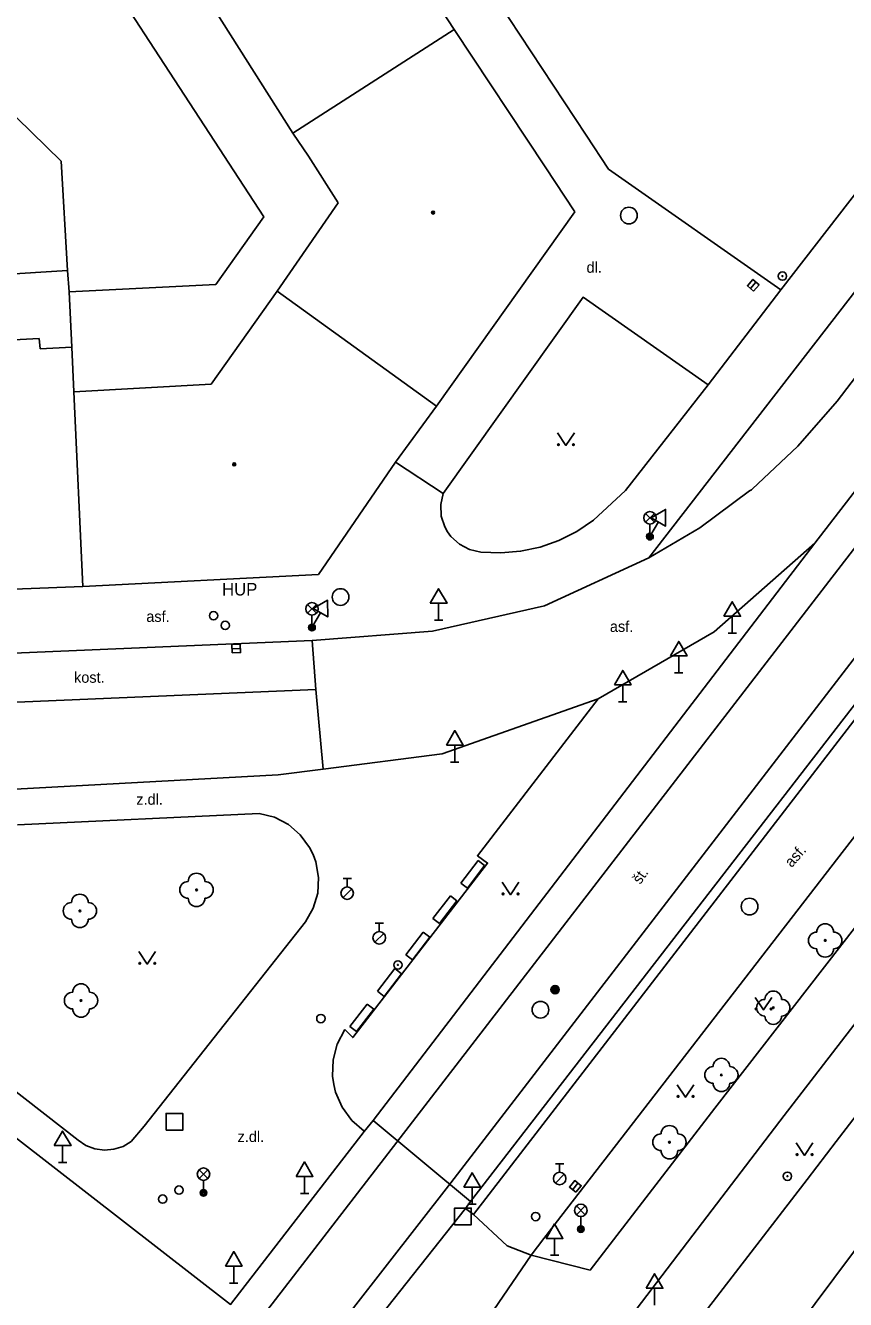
# Model space of a CAD drawing. Extents: x -598932 to -598196, y -1162207 to -1161504.
# Drawn here: x -598832.1 to -598782.9, y -1162047.2 to -1161970.8 of the extents above; entities that cross this region are included whole.
import ezdxf

# ---------------------------------------------------------------- set-up
doc = ezdxf.new("R2010")
doc.units = 0
for name, color, linetype in [('Level 22', 7, 'Continuous'), ('Level 25', 7, 'Continuous'), ('Level 26', 7, 'Continuous'), ('Level 27', 7, 'Continuous'), ('Level 28', 7, 'Continuous'), ('Level 33', 7, 'Continuous'), ('Level 34', 7, 'Continuous'), ('Level 36', 7, 'Continuous'), ('Level 39', 7, 'Continuous'), ('specificka linie pasportu komunikaci', 7, 'Continuous'), ('TM - budovy zdene_ betonove - VP', 7, 'Continuous'), ('TM - chodniky - VP', 7, 'Continuous'), ('TM - komunikace - VP', 7, 'Continuous'), ('TM - MHD - osa koleji', 7, 'Continuous'), ('TM - popis objektu', 7, 'Continuous'), ('TM - popis povrchu', 7, 'Continuous'), ('TM - rozhrani ploch obecne - VP', 7, 'Continuous')]:
    doc.layers.add(name, color=color, linetype=linetype)

msp = doc.modelspace()

# ---------------------------------------------------------------- linework, layer by layer
at = {"layer": 'Level 22'}
for centre in [(-598821.81, -1162022.62), (-598828.8, -1162023.88), (-598784.14, -1162025.65), (-598828.73, -1162029.25), (-598787.25, -1162029.68), (-598790.36, -1162033.71), (-598793.47, -1162037.74)]:
    msp.add_circle(centre, 0.05, dxfattribs=at)
for centre, start, end in [((-598821.81, -1162022.12), 0, 180), ((-598822.31, -1162022.62), 90, 270), ((-598821.31, -1162022.62), 270, 90), ((-598828.8, -1162023.38), 0, 180), ((-598821.81, -1162023.12), 180, 0), ((-598829.3, -1162023.88), 90, 270), ((-598828.3, -1162023.88), 270, 90), ((-598828.8, -1162024.38), 180, 0), ((-598784.14, -1162025.15), 0, 180), ((-598784.64, -1162025.65), 90, 270), ((-598783.64, -1162025.65), 270, 90), ((-598784.14, -1162026.15), 180, 0), ((-598828.73, -1162028.75), 0, 180), ((-598829.23, -1162029.25), 90, 270), ((-598828.23, -1162029.25), 270, 90), ((-598787.75, -1162029.68), 90, 270), ((-598787.25, -1162029.18), 0, 180), ((-598786.75, -1162029.68), 270, 90), ((-598828.73, -1162029.75), 180, 0), ((-598787.25, -1162030.18), 180, 0), ((-598790.36, -1162033.21), 0, 180), ((-598790.86, -1162033.71), 90, 270), ((-598789.86, -1162033.71), 270, 90), ((-598790.36, -1162034.21), 180, 0), ((-598793.47, -1162037.24), 0, 180), ((-598793.97, -1162037.74), 90, 270), ((-598792.97, -1162037.74), 270, 90), ((-598793.47, -1162038.24), 180, 0)]:
    msp.add_arc(centre, 0.5, start, end, dxfattribs=at)
at = {"layer": 'Level 25'}
for centre, radius in [((-598786.7, -1161985.84), 0.25), ((-598786.7, -1161985.84), 0.0303), ((-598809.74, -1162027.12), 0.25), ((-598809.74, -1162027.12), 0.0303), ((-598800.32, -1162028.6), 0.25), ((-598800.32, -1162028.6), 0.2), ((-598800.32, -1162028.6), 0.15), ((-598800.32, -1162028.6), 0.1), ((-598800.32, -1162028.6), 0.05), ((-598786.4, -1162039.78), 0.25), ((-598786.4, -1162039.78), 0.0303)]:
    msp.add_circle(centre, radius, dxfattribs=at)
at = {"layer": 'Level 26'}
for points in [[(-598823.63, -1162037.02), (-598822.63, -1162037.02), (-598822.63, -1162036.02), (-598823.63, -1162036.02)], [(-598806.35, -1162042.69), (-598805.35, -1162042.69), (-598805.35, -1162041.69), (-598806.35, -1162041.69)]]:
    msp.add_lwpolyline(points, close=True, dxfattribs=at)
at = {"layer": 'Level 27'}
for p, q in [((-598788.615, -1161986.578), (-598788.285, -1161986.202)), ((-598819.68, -1162008.169), (-598819.18, -1162008.15)), ((-598799.267, -1162040.584), (-598798.953, -1162040.196))]:
    msp.add_line(p, q, dxfattribs=at)
for points in [[(-598788.426, -1161986.743), (-598788.097, -1161986.366), (-598788.474, -1161986.037), (-598788.803, -1161986.414)], [(-598819.67, -1162008.419), (-598819.171, -1162008.4), (-598819.19, -1162007.901), (-598819.689, -1162007.92)], [(-598799.073, -1162040.742), (-598798.758, -1162040.353), (-598799.147, -1162040.038), (-598799.462, -1162040.427)]]:
    msp.add_lwpolyline(points, close=True, dxfattribs=at)
for centre in [(-598795.9, -1161982.21), (-598813.18, -1162005.07), (-598788.67, -1162023.62), (-598801.2, -1162029.8)]:
    msp.add_circle(centre, 0.5, dxfattribs=at)
at = {"layer": 'Level 28'}
for p, q in [((-598813.03, -1162021.945), (-598812.53, -1162021.945)), ((-598812.78, -1162022.445), (-598812.78, -1162021.945)), ((-598813.038, -1162023.092), (-598812.508, -1162022.562)), ((-598811.11, -1162024.615), (-598810.61, -1162024.615)), ((-598810.86, -1162025.115), (-598810.86, -1162024.615)), ((-598811.118, -1162025.762), (-598810.588, -1162025.232)), ((-598800.3, -1162039.045), (-598799.8, -1162039.045)), ((-598800.05, -1162039.545), (-598800.05, -1162039.045)), ((-598800.308, -1162040.192), (-598799.778, -1162039.662))]:
    msp.add_line(p, q, dxfattribs=at)
for centre, radius in [((-598820.79, -1162006.19), 0.25), ((-598820.09, -1162006.77), 0.25), ((-598812.78, -1162022.82), 0.375), ((-598810.86, -1162025.49), 0.375), ((-598814.36, -1162030.33), 0.25), ((-598800.05, -1162039.92), 0.375), ((-598822.86, -1162040.61), 0.25), ((-598823.84, -1162041.15), 0.25), ((-598801.49, -1162042.2), 0.25)]:
    msp.add_circle(centre, radius, dxfattribs=at)
at = {"layer": 'Level 33'}
for p, q in [((-598794.905, -1162000.59), (-598794.375, -1162000.06)), ((-598794.905, -1162000.06), (-598794.375, -1162000.59)), ((-598794.64, -1162000.7), (-598794.64, -1162001.45)), ((-598815.155, -1162006.04), (-598814.625, -1162005.51)), ((-598815.155, -1162005.51), (-598814.625, -1162006.04)), ((-598814.89, -1162006.15), (-598814.89, -1162006.9)), ((-598821.655, -1162039.92), (-598821.125, -1162039.39)), ((-598821.655, -1162039.39), (-598821.125, -1162039.92)), ((-598821.39, -1162040.03), (-598821.39, -1162040.78)), ((-598799.045, -1162042.09), (-598798.515, -1162041.56)), ((-598799.045, -1162041.56), (-598798.515, -1162042.09)), ((-598798.78, -1162042.2), (-598798.78, -1162042.95))]:
    msp.add_line(p, q, dxfattribs=at)
for centre, radius in [((-598794.64, -1162000.325), 0.375), ((-598794.64, -1162001.45), 0.2), ((-598794.64, -1162001.45), 0.145), ((-598794.64, -1162001.45), 0.0876), ((-598814.89, -1162005.775), 0.375), ((-598814.89, -1162006.9), 0.2), ((-598814.89, -1162006.9), 0.145), ((-598814.89, -1162006.9), 0.0876), ((-598821.39, -1162039.655), 0.375), ((-598821.39, -1162040.78), 0.2), ((-598821.39, -1162040.78), 0.145), ((-598821.39, -1162040.78), 0.0876), ((-598798.78, -1162041.825), 0.375), ((-598798.78, -1162042.95), 0.2), ((-598798.78, -1162042.95), 0.145), ((-598798.78, -1162042.95), 0.0876)]:
    msp.add_circle(centre, radius, dxfattribs=at)
at = {"layer": 'Level 34'}
for p, q in [((-598794.133, -1162000.567), (-598794.64, -1162001.45)), ((-598794.857, -1162001.326), (-598794.423, -1162001.574)), ((-598807.3, -1162005.442), (-598807.3, -1162006.46)), ((-598814.383, -1162006.017), (-598814.89, -1162006.9)), ((-598807.55, -1162006.46), (-598807.05, -1162006.46)), ((-598789.71, -1162006.222), (-598789.71, -1162007.24)), ((-598815.107, -1162006.776), (-598814.673, -1162007.024)), ((-598789.96, -1162007.24), (-598789.46, -1162007.24)), ((-598792.91, -1162008.602), (-598792.91, -1162009.62)), ((-598793.16, -1162009.62), (-598792.66, -1162009.62)), ((-598796.27, -1162010.332), (-598796.27, -1162011.35)), ((-598796.52, -1162011.35), (-598796.02, -1162011.35)), ((-598806.34, -1162013.942), (-598806.34, -1162014.96)), ((-598806.59, -1162014.96), (-598806.09, -1162014.96)), ((-598829.83, -1162037.942), (-598829.83, -1162038.96)), ((-598830.08, -1162038.96), (-598829.58, -1162038.96)), ((-598815.33, -1162039.792), (-598815.33, -1162040.81)), ((-598815.58, -1162040.81), (-598815.08, -1162040.81)), ((-598805.3, -1162040.442), (-598805.3, -1162041.46)), ((-598805.55, -1162041.46), (-598805.05, -1162041.46)), ((-598800.35, -1162043.502), (-598800.35, -1162044.52)), ((-598800.6, -1162044.52), (-598800.1, -1162044.52)), ((-598819.58, -1162045.162), (-598819.58, -1162046.18)), ((-598819.83, -1162046.18), (-598819.33, -1162046.18)), ((-598794.359, -1162046.492), (-598794.36, -1162047.51))]:
    msp.add_line(p, q, dxfattribs=at)
for points in [[(-598794.567, -1162000.318), (-598793.7, -1162000.816), (-598793.702, -1161999.816)], [(-598807.8, -1162005.442), (-598806.8, -1162005.442), (-598807.3, -1162004.576)], [(-598814.817, -1162005.768), (-598813.95, -1162006.266), (-598813.952, -1162005.266)], [(-598790.21, -1162006.222), (-598789.21, -1162006.222), (-598789.71, -1162005.356)], [(-598793.41, -1162008.602), (-598792.41, -1162008.602), (-598792.91, -1162007.736)], [(-598796.77, -1162010.332), (-598795.77, -1162010.332), (-598796.27, -1162009.466)], [(-598806.84, -1162013.942), (-598805.84, -1162013.942), (-598806.34, -1162013.076)], [(-598830.33, -1162037.942), (-598829.33, -1162037.942), (-598829.83, -1162037.076)], [(-598815.83, -1162039.792), (-598814.83, -1162039.792), (-598815.33, -1162038.926)], [(-598805.8, -1162040.442), (-598804.8, -1162040.442), (-598805.3, -1162039.576)], [(-598800.85, -1162043.502), (-598799.85, -1162043.502), (-598800.35, -1162042.636)], [(-598820.08, -1162045.162), (-598819.08, -1162045.162), (-598819.58, -1162044.296)], [(-598794.859, -1162046.492), (-598793.859, -1162046.492), (-598794.359, -1162045.626)]]:
    msp.add_lwpolyline(points, close=True, dxfattribs=at)
at = {"layer": 'Level 36'}
for points in [[(-598800.17, -1161995.24), (-598799.67, -1161995.99), (-598799.17, -1161995.24)], [(-598803.49, -1162022.16), (-598802.99, -1162022.91), (-598802.49, -1162022.16)], [(-598825.26, -1162026.32), (-598824.76, -1162027.07), (-598824.26, -1162026.32)], [(-598788.33, -1162029.06), (-598787.83, -1162029.81), (-598787.33, -1162029.06)], [(-598793, -1162034.3), (-598792.5, -1162035.05), (-598792, -1162034.3)], [(-598785.87, -1162037.78), (-598785.37, -1162038.53), (-598784.87, -1162037.78)]]:
    msp.add_lwpolyline(points, dxfattribs=at)
for centre in [(-598800.12, -1161995.94), (-598799.221, -1161995.94), (-598803.44, -1162022.86), (-598802.541, -1162022.86), (-598825.21, -1162027.02), (-598824.311, -1162027.02), (-598788.28, -1162029.76), (-598787.381, -1162029.76), (-598792.95, -1162035), (-598792.051, -1162035), (-598785.82, -1162038.48), (-598784.921, -1162038.48)]:
    msp.add_circle(centre, 0.05, dxfattribs=at)
at = {"layer": 'Level 39'}
for centre, radius in [((-598807.63, -1161982.03), 0.09), ((-598807.63, -1161982.03), 0.0398), ((-598819.55, -1161997.12), 0.09), ((-598819.55, -1161997.12), 0.0398)]:
    msp.add_circle(centre, radius, dxfattribs=at)
at = {"layer": 'specificka linie pasportu komunikaci'}
for points in [[(-598814.22, -1162015.38), (-598814.66, -1162010.61)], [(-598785.92, -1162048.98), (-598775.483, -1162035.027), (-598774.992, -1162034.371), (-598769.53, -1162027.073), (-598769.53, -1162027.07)], [(-598813.9, -1162052.09), (-598805.7, -1162041.71)], [(-598803.19, -1162043.96), (-598805.22, -1162042.08)], [(-598801.76, -1162044.51), (-598803.19, -1162043.96)]]:
    msp.add_lwpolyline(points, dxfattribs=at)
at = {"layer": 'TM - budovy zdene_ betonove - VP'}
for points in [[(-598816.04, -1161977.27), (-598825.31, -1161962.63)], [(-598811.5, -1161963.22), (-598806.37, -1161971.07)], [(-598806.37, -1161971.07), (-598816.04, -1161977.27)], [(-598806.37, -1161971.07), (-598800.92, -1161979.29), (-598799.14, -1161981.98)], [(-598815.09, -1161978.66), (-598816.04, -1161977.27)], [(-598813.32, -1161981.44), (-598815.09, -1161978.66)], [(-598816.98, -1161986.74), (-598813.32, -1161981.44)], [(-598799.14, -1161981.98), (-598807.43, -1161993.63)], [(-598820.93, -1161992.32), (-598816.98, -1161986.74)], [(-598807.43, -1161993.63), (-598816.98, -1161986.74)], [(-598836.62, -1161989.85), (-598831.24, -1161989.57)], [(-598831.24, -1161989.57), (-598831.18, -1161990.2)], [(-598831.18, -1161990.2), (-598829.29, -1161990.1)], [(-598829.29, -1161990.1), (-598829.17, -1161992.77)], [(-598829.17, -1161992.77), (-598820.93, -1161992.32)], [(-598828.63, -1162004.44), (-598829.17, -1161992.77)], [(-598807.43, -1161993.63), (-598809.88, -1161996.98)], [(-598809.88, -1161996.98), (-598814.51, -1162003.72)], [(-598814.51, -1162003.72), (-598828.63, -1162004.44)], [(-598828.63, -1162004.44), (-598844.65, -1162005.06)]]:
    msp.add_lwpolyline(points, dxfattribs=at)
at = {"layer": 'TM - chodniky - VP'}
for points in [[(-598807.03, -1161964.38), (-598798.47, -1161977.39), (-598797.13, -1161979.43), (-598786.79, -1161986.67)], [(-598786.79, -1161986.67), (-598781.28, -1161979.55)], [(-598778.8, -1161982.18), (-598794.7, -1162002.73)], [(-598791.15, -1161992.36), (-598798.65, -1161987.11), (-598807.03, -1161998.86)], [(-598798.03, -1162000.47), (-598796.1, -1161998.68), (-598791.15, -1161992.36)], [(-598804.78, -1162002.38), (-598805.45, -1162002.23), (-598806.059, -1162001.913), (-598806.565, -1162001.449), (-598806.77, -1162001.17), (-598806.935, -1162000.871), (-598807.143, -1162000.217), (-598807.175, -1161999.531), (-598807.03, -1161998.86)], [(-598798.03, -1162000.47), (-598799.022, -1162001.141), (-598800.091, -1162001.681), (-598801.22, -1162002.08), (-598802.39, -1162002.332), (-598803.584, -1162002.432), (-598804.78, -1162002.38)], [(-598811.23, -1162036.45), (-598784.75, -1162001.85)], [(-598812.93, -1162030.99), (-598812.45, -1162031.47), (-598804.37, -1162021.01), (-598804.98, -1162020.58), (-598797.75, -1162011.18)], [(-598832.53, -1162018.72), (-598818.06, -1162018.04)], [(-598818.06, -1162018.04), (-598817.145, -1162018.271), (-598816.307, -1162018.703), (-598815.59, -1162019.316), (-598815.031, -1162020.076), (-598814.82, -1162020.5), (-598814.66, -1162020.943), (-598814.496, -1162021.872), (-598814.549, -1162022.814), (-598814.815, -1162023.719), (-598815.28, -1162024.54)], [(-598798.23, -1162045.41), (-598790.75, -1162035.71), (-598780.44, -1162022.41)], [(-598815.28, -1162024.54), (-598824.94, -1162036.78)], [(-598786.59, -1162036.14), (-598777.36, -1162024.17)], [(-598828.91, -1162037.61), (-598837.27, -1162031.1)], [(-598811.77, -1162037.09), (-598811.773, -1162037.085), (-598812.509, -1162036.438), (-598813.085, -1162035.647), (-598813.474, -1162034.749), (-598813.59, -1162034.28), (-598813.656, -1162033.787), (-598813.624, -1162032.808), (-598813.378, -1162031.861), (-598812.93, -1162030.99)], [(-598786.59, -1162036.14), (-598792.07, -1162043.32)], [(-598824.94, -1162036.78), (-598825.716, -1162037.696), (-598826.209, -1162037.991), (-598826.756, -1162038.168), (-598827.328, -1162038.217), (-598827.897, -1162038.137), (-598828.434, -1162037.931), (-598828.91, -1162037.61)], [(-598792.07, -1162043.32), (-598802.19, -1162056.59)], [(-598798.23, -1162045.41), (-598801.76, -1162044.51)]]:
    msp.add_lwpolyline(points, dxfattribs=at)
at = {"layer": 'TM - komunikace - VP'}
for points in [[(-598776.65, -1161984.47), (-598783.43, -1161993.33)], [(-598773.73, -1161987.57), (-598784.75, -1162001.85)], [(-598788.56, -1161998.64), (-598788.521, -1161998.6), (-598785.77, -1161996.04), (-598783.43, -1161993.33)], [(-598805.39, -1162041.3), (-598805.7, -1162041.71), (-598805.22, -1162042.08), (-598767.95, -1161993.7)], [(-598764.96, -1161996.88), (-598800.99, -1162043.52), (-598801.76, -1162044.51)], [(-598794.7, -1162002.73), (-598791.659, -1162000.923), (-598788.671, -1161998.714), (-598788.56, -1161998.64)], [(-598784.75, -1162001.85), (-598790.8, -1162007.15)], [(-598800.95, -1162005.59), (-598794.7, -1162002.73)], [(-598807.66, -1162007.12), (-598800.95, -1162005.59)], [(-598814.88, -1162007.68), (-598807.66, -1162007.12)], [(-598790.8, -1162007.15), (-598797.75, -1162011.18)], [(-598841.73, -1162008.82), (-598814.88, -1162007.68)], [(-598797.75, -1162011.18), (-598807.09, -1162014.46)], [(-598807.09, -1162014.46), (-598814.22, -1162015.38), (-598816.91, -1162015.72)], [(-598816.91, -1162015.72), (-598832.68, -1162016.59)], [(-598792.13, -1162048.94), (-598785.22, -1162039.97), (-598783.48, -1162037.69), (-598777.75, -1162030.25)], [(-598838.9, -1162032.64), (-598834.74, -1162035.86), (-598819.77, -1162047.46), (-598811.77, -1162037.09)], [(-598811.77, -1162037.09), (-598811.23, -1162036.45)], [(-598811.23, -1162036.45), (-598805.39, -1162041.3)], [(-598801.76, -1162044.51), (-598804.55, -1162048.6)]]:
    msp.add_lwpolyline(points, dxfattribs=at)
at = {"layer": 'TM - MHD - osa koleji'}
for points in [[(-598772.31, -1161989.08), (-598809.8, -1162037.73), (-598829.26, -1162062.96)], [(-598769.53, -1161992.03), (-598806.58, -1162040.17), (-598826.1, -1162065.26)]]:
    msp.add_lwpolyline(points, dxfattribs=at)
at = {"layer": 'TM - rozhrani ploch obecne - VP'}
for points in [[(-598832.33, -1161959.93), (-598817.78, -1161982.28), (-598820.66, -1161986.35), (-598829.45, -1161986.79)], [(-598843.27, -1161965.91), (-598829.92, -1161978.95), (-598829.55, -1161985.5)], [(-598845.77, -1161986.52), (-598829.55, -1161985.5)], [(-598829.55, -1161985.5), (-598829.45, -1161986.79)], [(-598829.45, -1161986.79), (-598829.29, -1161990.1)], [(-598786.79, -1161986.67), (-598791.15, -1161992.36)], [(-598805.39, -1162041.3), (-598768.31, -1161993.32)], [(-598807.03, -1161998.86), (-598809.88, -1161996.98)], [(-598814.88, -1162007.68), (-598814.66, -1162010.61), (-598841.54, -1162011.75), (-598841.73, -1162008.82)], [(-598805.98, -1162022.21), (-598804.94, -1162020.86)], [(-598804.94, -1162020.86), (-598804.55, -1162021.16)], [(-598804.55, -1162021.16), (-598805.58, -1162022.51)], [(-598805.58, -1162022.51), (-598805.98, -1162022.21)], [(-598807.64, -1162024.33), (-598806.6, -1162022.98)], [(-598806.6, -1162022.98), (-598806.21, -1162023.28)], [(-598806.21, -1162023.28), (-598807.24, -1162024.63)], [(-598807.24, -1162024.63), (-598807.64, -1162024.33)], [(-598809.27, -1162026.51), (-598808.23, -1162025.16)], [(-598807.83, -1162025.46), (-598808.87, -1162026.81)], [(-598808.23, -1162025.16), (-598807.83, -1162025.46)], [(-598808.87, -1162026.81), (-598809.27, -1162026.51)], [(-598810.97, -1162028.69), (-598809.93, -1162027.34)], [(-598809.53, -1162027.65), (-598810.57, -1162029)], [(-598809.93, -1162027.34), (-598809.53, -1162027.65)], [(-598810.57, -1162029), (-598810.97, -1162028.69)], [(-598812.62, -1162030.81), (-598811.58, -1162029.46)], [(-598811.18, -1162029.77), (-598812.22, -1162031.11)], [(-598811.58, -1162029.46), (-598811.18, -1162029.77)], [(-598812.22, -1162031.11), (-598812.62, -1162030.81)]]:
    msp.add_lwpolyline(points, dxfattribs=at)

# ---------------------------------------------------------------- texts
at = {"layer": 'TM - popis objektu'}
msp.add_text('HUP', height=0.75, dxfattribs=at).set_placement((-598820.28, -1162004.98))
at = {"layer": 'TM - popis povrchu'}
for s, p in [('dl.', (-598798.44, -1161985.64)), ('asf.', (-598824.82, -1162006.56)), ('asf.', (-598797.04, -1162007.16)), ('kost.', (-598829.15, -1162010.21)), ('z.dl.', (-598825.42, -1162017.52)), ('z.dl.', (-598819.35, -1162037.73))]:
    msp.add_text(s, height=0.65, dxfattribs=at).set_placement(p)
for s, rotation, p in [('asf.', 48.58, (-598786.15, -1162021.32)), ('št.', 55.26, (-598795.22, -1162022.33))]:
    msp.add_text(s, height=0.65, rotation=rotation, dxfattribs=at).set_placement(p)

doc.saveas('drawing.dxf')
